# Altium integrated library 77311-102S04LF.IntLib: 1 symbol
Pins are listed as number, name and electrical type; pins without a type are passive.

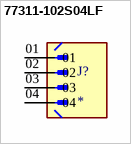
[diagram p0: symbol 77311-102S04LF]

## 77311-102S04LF
designator J?
BergStikÂ® 2.54mm, Board To Board, Unshrouded Header, 2.54 mm Pitch, Vertical, Single Row,Through Hole, 4 positions.; MF: Amphenol ICC (FCI); MP: 77311-102S04LF
footprint AMPHENOL_77311-102S04LF
pins: 01, 02, 03, 04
